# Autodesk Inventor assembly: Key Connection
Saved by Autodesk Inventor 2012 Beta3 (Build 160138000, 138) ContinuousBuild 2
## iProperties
Created: 2010-12
Part Number: Key Connection
Document SubType Name: Assembly
Designer: Beta-8540w
ClientObjectVersion: 1
Author: Beta-8540w
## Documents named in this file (2)
- C:\Inventor 2012 Essentials\Assemblies\Chapter 6\c6-01\Design Accelerator\Key Connection1.iam
- C:\Inventor 2012 Essentials\Content Center Files\en-US\DIN 6885  A\DIN 6885 - A 4 x 4 x 12.ipt
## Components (1 placed, 1 different names)
1. DIN 6885 A A 4 x 4 x 12:1
